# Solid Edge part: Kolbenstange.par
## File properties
Username: bmolnar
Dokumentum tartalom típus: 0
Author: bmolnar
Last saved by: bmolnar
Revision: 94
Sűrűség: 0,000 kg/m^3
Pontosság: 0,990
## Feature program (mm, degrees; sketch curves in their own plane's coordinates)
base feature "unnamed BaseFeature 1"
sketch for "unnamed Protrusion 1" plane through (61.5, 0, 0) normal (1, 0, 0) x-axis (0, 0, 1)
  circle centre (0, 0) radius 40
extrude "unnamed Protrusion 1" add finite 19.5 along +normal
sketch for "Kihúzás_2" plane through (61.5, 0, 0) normal (1, 0, 0) x-axis (0, 0, 1)
  circle centre (0, 0) radius 40
extrude "Kihúzás_2" add finite 4.5 along -normal
thread "unnamed Thread 1"
chamfer "Letörés_1" setback 3.3  SetBackValue2 = 20 deg
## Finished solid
Body 1: solid body, 17 faces, 23 edges, 8 vertices.
  Faces by surface: plane 8, cylinder 4, torus 3, cone 2
  Edges by curve: circle 13, line 6, ellipse 2, intersection 2
Bounding box of the edges (mm; curved faces can reach further): 236.000 x 80.000 x 80.000, from (-155, -40, -40) to (81, 40, 40).
Cylindrical faces by radius (mm): R6.75 x1, R8 x1, R10 x1, R40 x1
Conical faces (half-angle, radius in mm at the cone's reference point): 20 deg R6.7989 x1, 60 deg R7.475 x1
Toroidal faces (ring radius, tube radius in mm): R7.15 r0.4 x2, R8.2 r1.8 x1
Planar faces by outward normal: +x 1, +y 1, -x 3, -y 1, oblique 2
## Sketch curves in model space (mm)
circle centre (61.5, 0, 0) radius 40
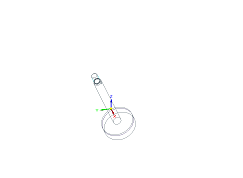
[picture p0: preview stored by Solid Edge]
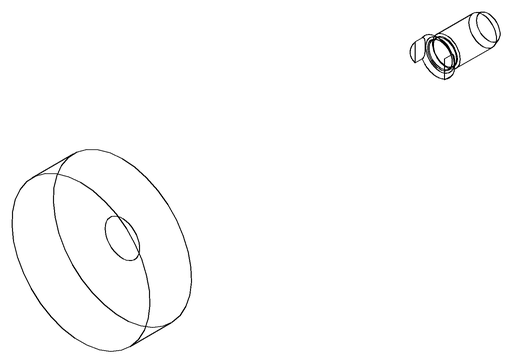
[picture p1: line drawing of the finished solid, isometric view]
